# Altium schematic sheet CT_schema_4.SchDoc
size 349 x 348 mm
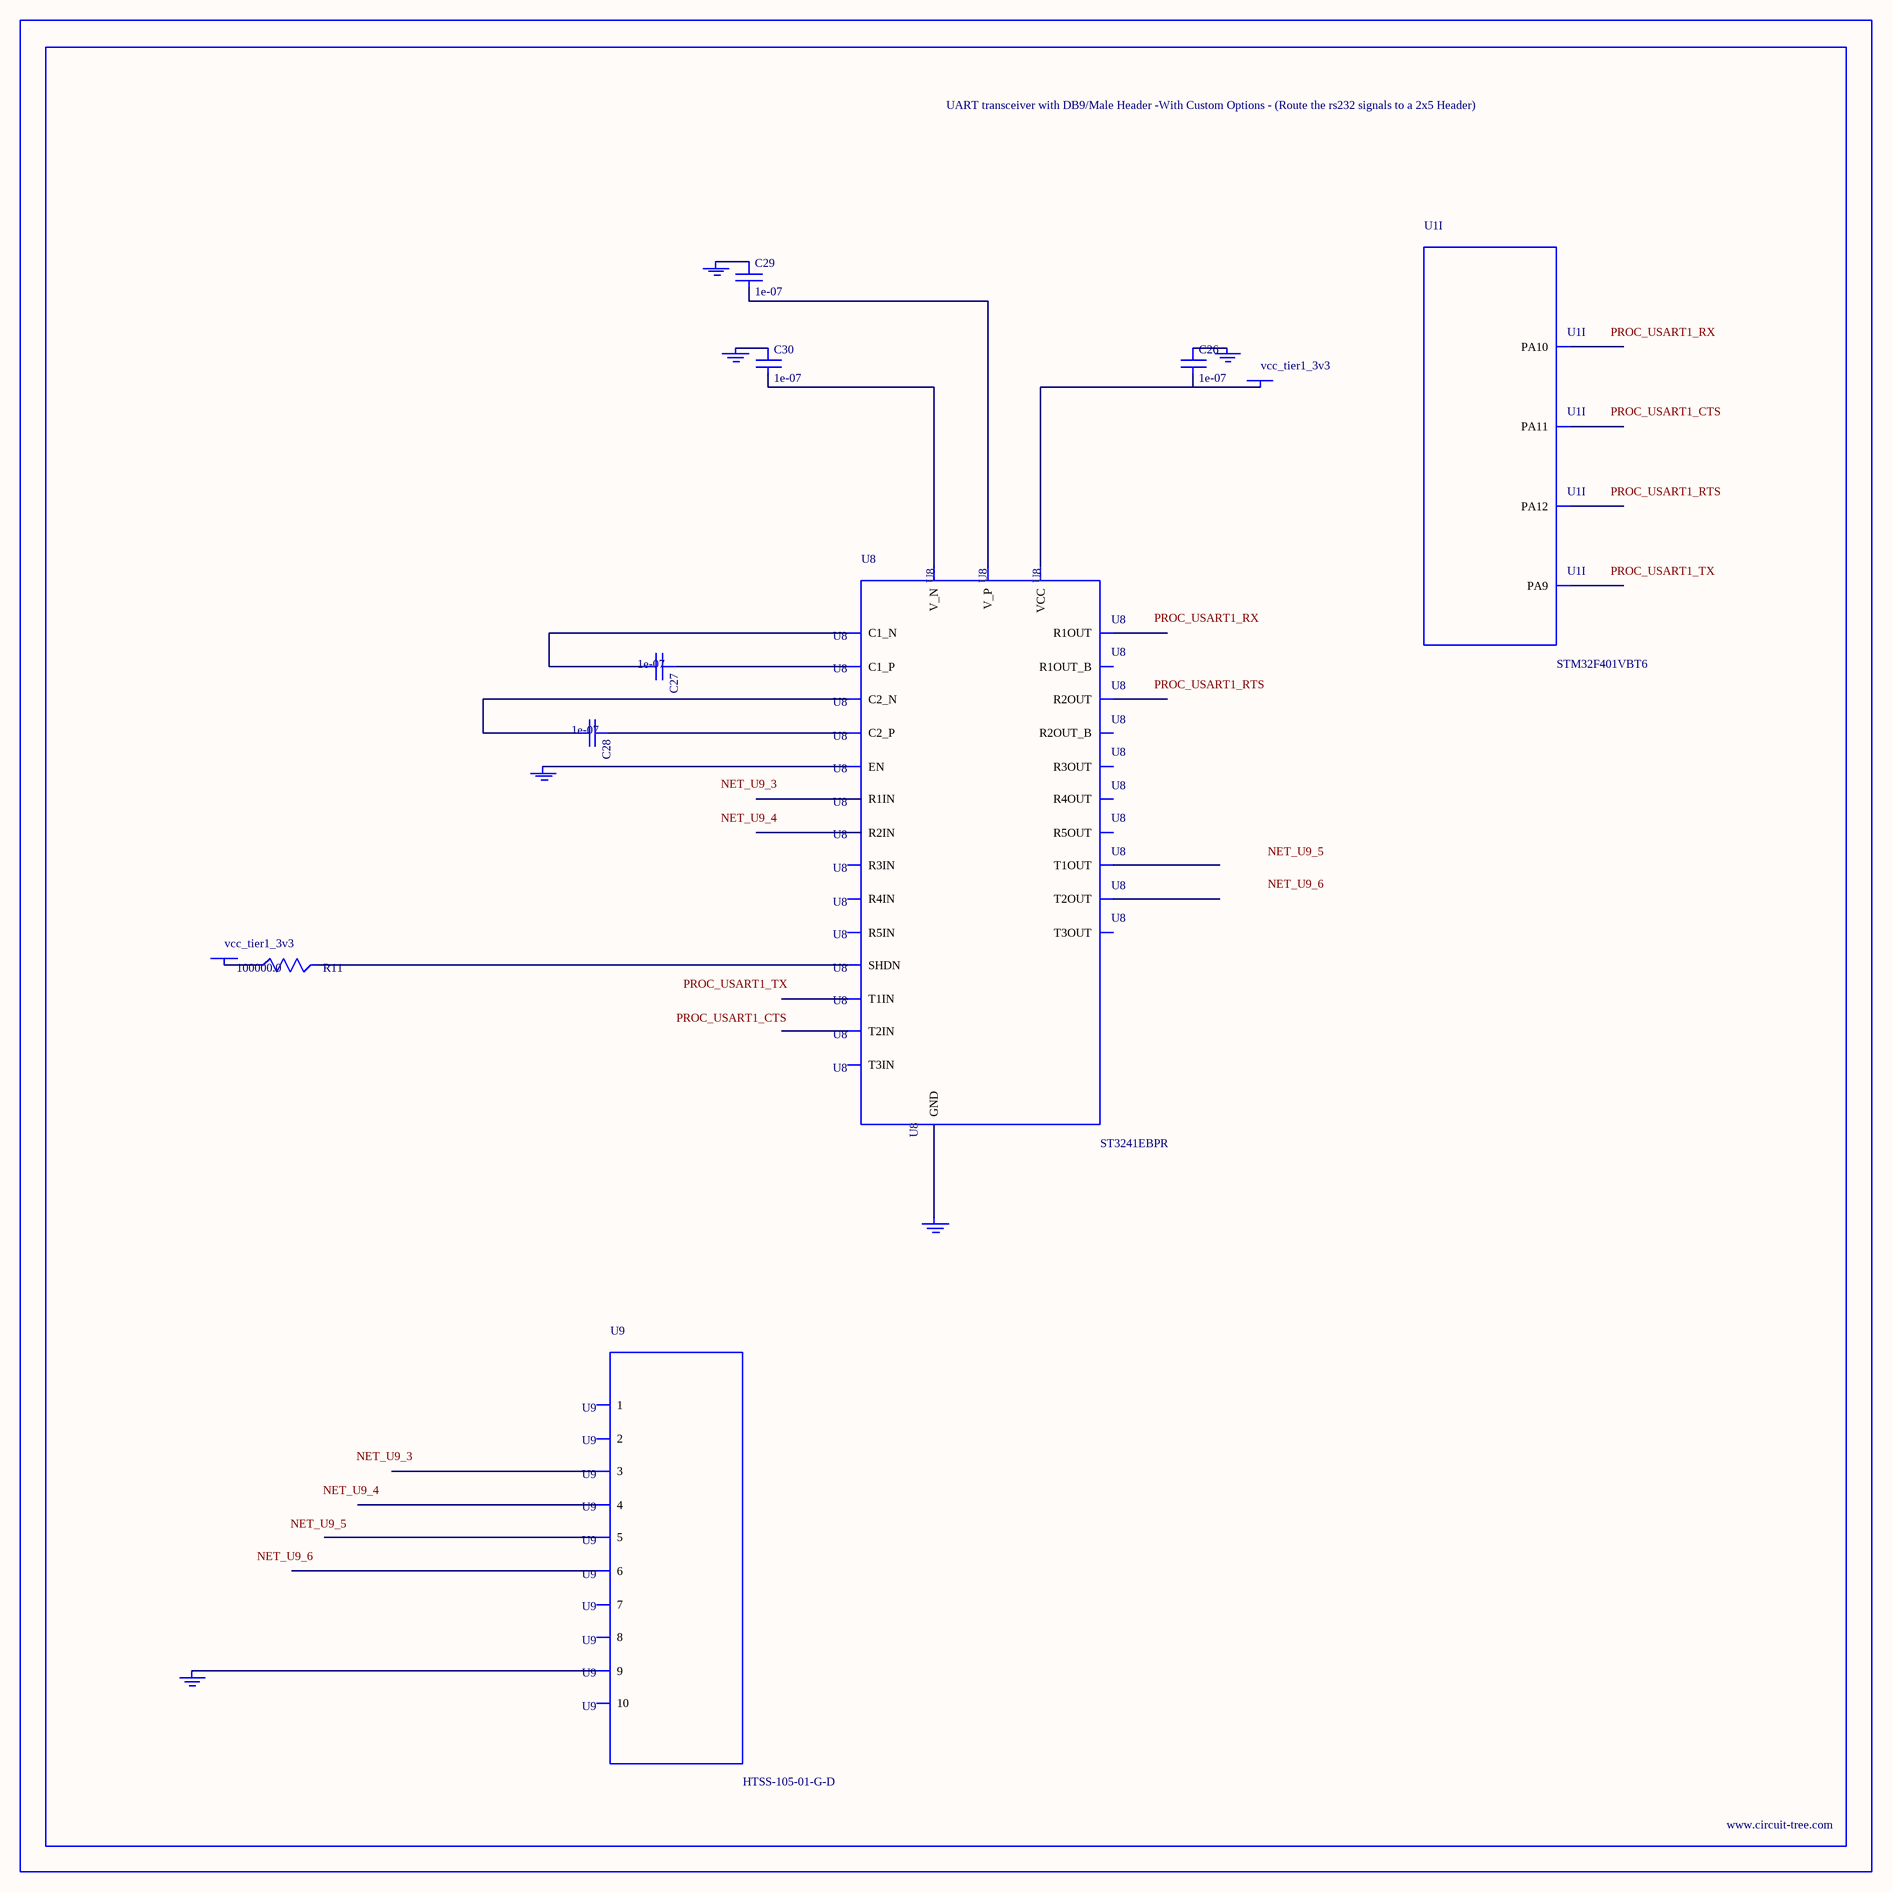
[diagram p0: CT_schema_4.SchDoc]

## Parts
BORDER3  (no value)
C26  1e-07  [C0402]
C27  1e-07  [C0402]
C28  1e-07  [C0402]
C29  1e-07  [C0402]
C30  1e-07  [C0402]
GND_INSTANCE_3_0  (no value)
GND_INSTANCE_3_1  (no value)
GND_INSTANCE_3_2  (no value)
GND_INSTANCE_3_3  (no value)
GND_INSTANCE_3_4  (no value)
GND_INSTANCE_3_5  (no value)
POWER_INSTANCE_3_0  vcc_tier1_3v3
POWER_INSTANCE_3_1  vcc_tier1_3v3
R11  100000.0  [R0603]
U1  STM32F401VBT6  [LQFP100]  (part I of 10)
U8  ST3241EBPR  [SSOP-28]
U9  HTSS-105-01-G-D  [HTSS-105-01-G-D]

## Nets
NetC26_1: C26.1 GND_INSTANCE_3_2.0(GND)
NetC26_2: C26.2 POWER_INSTANCE_3_1.0(PWR) U8.26(VCC)
NetC27_1: C27.1 U8.28(C1_P)
NetC27_2: C27.2 U8.24(C1_N)
NetC28_1: C28.1 U8.1(C2_P)
NetC28_2: C28.2 U8.2(C2_N)
NetC29_1: C29.1 GND_INSTANCE_3_3.0(GND)
NetC29_2: C29.2 U8.27(V_P)
NetC30_1: C30.1 GND_INSTANCE_3_0.0(GND)
NetC30_2: C30.2 U8.3(V_N)
NetGND_INSTANCE_3_1_0: GND_INSTANCE_3_1.0(GND) U8.23(EN)
NetGND_INSTANCE_3_4_0: GND_INSTANCE_3_4.0(GND) U8.25(GND)
NetGND_INSTANCE_3_5_0: GND_INSTANCE_3_5.0(GND) U9.9
NetPOWER_INSTANCE_3_0_0: POWER_INSTANCE_3_0.0(PWR) R11.1
NetR11_2: R11.2 U8.22(SHDN)

Not connected (* = marked no-connect by the designer): U1 68(PA9) 69(PA10) 70(PA11) 71(PA12); U8 4(R1IN) 5(R2IN) 6(R3IN) 7(R4IN) 8(R5IN) 9(T1OUT) 10(T2OUT) 11(T3OUT) 12(T3IN) 13(T2IN) 14(T1IN) 15(R5OUT) 16(R4OUT) 17(R3OUT) 18(R2OUT) 19(R1OUT) 20(R2OUT_B) 21(R1OUT_B); U9 1 2 3 4 5 6 7 8 10

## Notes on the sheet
- Labels drawn without touching a wire or pin: NET_U9_3, NET_U9_4, NET_U9_5, NET_U9_6, PROC_USART1_CTS, PROC_USART1_RTS, PROC_USART1_RX, PROC_USART1_TX

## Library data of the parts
BORDER3 = BORDER_PAGE3
C26-C30 = C0402C104K3RACTU
GND_INSTANCE_3_0-GND_INSTANCE_3_5 = GND
POWER_INSTANCE_3_0 POWER_INSTANCE_3_1 = PWR
R11 = RC0603JR-07100KL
